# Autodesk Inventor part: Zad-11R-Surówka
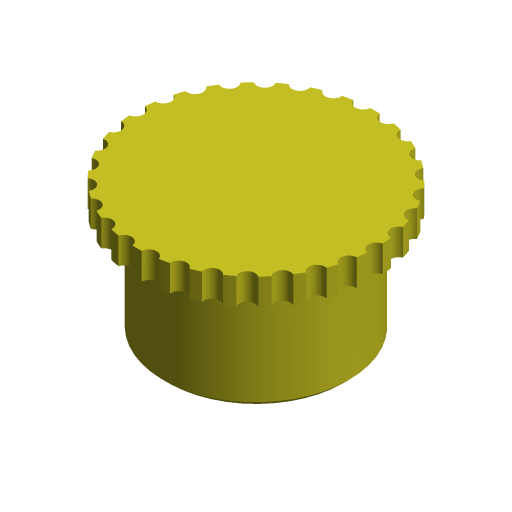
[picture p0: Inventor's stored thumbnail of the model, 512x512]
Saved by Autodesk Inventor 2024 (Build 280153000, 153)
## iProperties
Company: ATC
Shininess: 20.0
Length Units: 11269
Angle Units: 11279
Time Units: 11290
Mass Units: 11283
Length Display Precision: 3
Angle Display Precision: 2
Compacted: True
Created: 2023-03
Part Number: Zad-11R-Surówka
Document SubType Name: Modeling
Designer: Andrzej Jaskulski
Material: Kurs-AJ
Density: 1 g/cm^3
Appearance: Kanarkowa
Checked By: A.J.
Engr Approved By: Andrzej Jaskulski
Mfg Approved By: Andrzej Jaskulski
Authority: A.J.
Density: 0.0
Volumn: 0.0
Area: 0.0
PropertySet Name: Model Information
Control State: 0
Master: False
Checked Out: False
Title: A.J.: Kurs R2024-MEP
Author: Andrzej Jaskulski
Revision Number: 1/24
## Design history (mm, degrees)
sketch "Sketch1"
  geometry: C1 r 17.5 at (49.669, 110.237)
  constraints: 1 centre point, 1 other
  dimensions: "d1" = 35 diameter of C1
extrude "Korpus" new body sketch "Sketch1" distance "d2" = 20; taper "d3" = 0 deg
node "Oś symetrii"
extrude "Obrzeże" join distance "d5" = 5; taper "d6" = 0 deg
  node "Sketch2"
chamfer "Faza" distance "d7" = 1; stored, may be unused: second distance "d8" = 1, angle "d20" = 45 deg
sketch "Sketch3"
  geometry: 1 further point
node "Położenie otworu moletowania"
node "Sketch4"
hole "Otwór moletowania" sketch "Sketch3" diameter "d10" = 3; stored, may be unused: countersink angle "d14" = 60 deg, drill point angle "d16" = 118 deg; dims "d11" = 6, "d12" = 4, "d13" = 2, "d15" = 8
node "Sketch5"
node "Bryła1"
node "Korpusy bryłowe"
node "Korpusy powierzchniowe"
pattern_circular "Moletowanie" dims angle "d19" = 360 deg
other parameters: "d0" = 35 (derived), "d4" = 0, "d9" = 0
